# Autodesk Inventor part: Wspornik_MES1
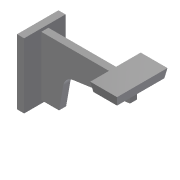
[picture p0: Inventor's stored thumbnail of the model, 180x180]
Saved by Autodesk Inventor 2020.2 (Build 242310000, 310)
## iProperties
Created: 2011-10
Part Number: Wspornik_MES1
Material: Stal
Document SubType Name: Modeling
Designer: F.Stasiak
Density: 7.85 g/cm^3
Mass: 1859.19 g
Surface Area: 481.94 cm^2
Volume: 236.84 cm^3
Appearance: Stal
Catalog Web Link: www.expertbooks.pl
Manager: www.cadconsulting.pl
Company: Fabian Stasiak CAD Consulting
Author: F.Stasiak
Subject: Zbiór ćwiczeń. Autodesk Inventor 2020. Kurs Professional
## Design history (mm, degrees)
sketch "Szkic1"
  geometry: L1 (0, 0)-(0, 100); L2 (0, 100)-(150, 100); L3 (150, 100)-(150, 70); L4 (150, 70)-(53.931, 56.328); L5 (37.053, 40)-(30, 0); L6 (30, 0)-(0, 0); L7 (10, 90)-(10, 10); L8 (10, 10)-(21.609, 10); L9 (21.609, 10)-(27.205, 41.736); L10 (52.522, 66.228)-(140, 78.678); L11 (140, 78.678)-(140, 90); L12 (140, 90)-(10, 90); C1 r 25 at (150, 85); C2 r 15 at (150, 85); A1 r 20 centre (56.749, 36.527) between (53.931, 56.328) and (37.053, 40); A2 r 30 centre (56.749, 36.527) between (52.522, 66.228) and (27.205, 41.736)
  constraints: 24 end point, 4 centre point, 4 perpendicular, 4 point on circle, 2 parallel, 2 tangent, 1 coincident, 1 midpoint, 1 vertical, 6 other
  dimensions: "d0" = 100 distance of L1.start L1.end; "d1" = 150 distance of L1.end L2.end; "d2" = 30 distance of L2.end L3.end; "d3" = 30 distance of L5.end L1.start; "d4" = 20 radius of A1; "d5" = 100 deg angle of L6 L5; "d6" = 40 vertical distance of L5.start L5.end; "d7" = 10 distance between parallel lines of L1 L7; "d20" = 50 diameter of C1; "d21" = 30 diameter of C2
extrude "Wyciągnięcie proste1" new body sketch "Szkic1" stored distance "d8" = 12; taper "d9" = 0 deg
sketch "Szkic3"
  geometry: L1 (0, 100)-(-12, 100) reference; L2 (-41, 105)-(29, 105); L3 (29, 105)-(29, -5); L4 (29, -5)-(-41, -5); L5 (-41, -5)-(-41, 105); 3 further points
  constraints: 8 end point, 2 midpoint, 2 parallel, 1 horizontal, 1 perpendicular, 1 vertical alignment
  dimensions: "d27" = 70 distance of L3.end L4.end; "d28" = 110 distance of L2.end L3.end; "d48" = 5 distance between parallel lines of L2 L1
extrude "Wyciągnięcie proste6" join sketch "Szkic3" distance "d29" = 12; taper "d30" = 0 deg
sketch "Szkic4"
  geometry: L1 (0, 0)-(0, 12) reference; L2 (12, 46)-(-28, 46); L3 (-28, 46)-(-28, -34); L4 (-28, -34)-(12, -34); L5 (12, -34)-(12, 46); 3 further points
  constraints: 8 end point, 2 midpoint, 2 parallel, 1 horizontal, 1 horizontal alignment, 1 perpendicular
  dimensions: "d31" = 40 distance of L4.end L3.end; "d32" = 80 distance of L3.end L2.end; "d40" = 12 distance between parallel lines of L5 L1
extrude "Wyciągnięcie proste7" join sketch "Szkic4" distance "d33" = 10; taper "d34" = 0 deg; dims "d49" = 5, "d50" = 0
feature "Pochylenie ściany1" dims angle "d53" = 10 deg
node "Bryła1"
